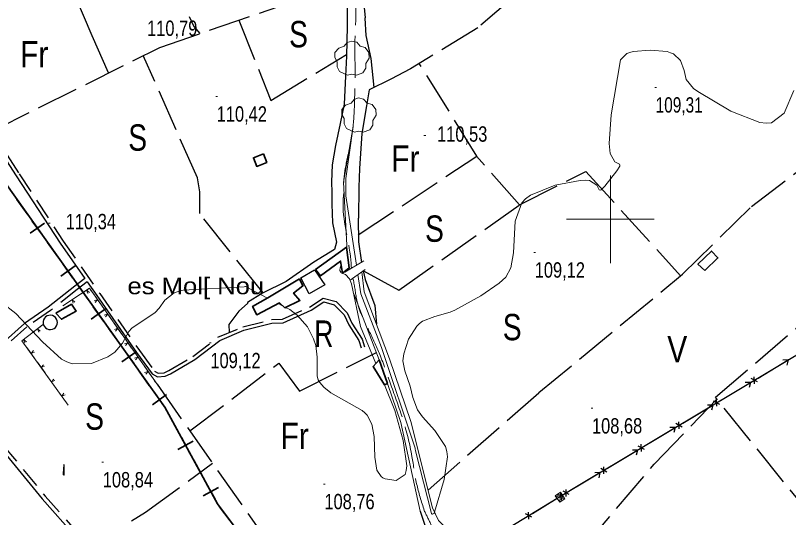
# Model space of a CAD drawing. Extents: x 483840 to 488445, y 4386047 to 4389027.
# Drawn here: x 486660.9 to 487101.5, y 4388330.1 to 4388616.1 of the extents above; entities that cross this region are included whole.
import ezdxf
from ezdxf.enums import TextEntityAlignment as Align

# ---------------------------------------------------------------- set-up
doc = ezdxf.new("R2010")
doc.units = 0
doc.header["$LTSCALE"] = 4
doc.linetypes.add('LONG_DASHED', pattern=[7.5, 6, -1.5])
doc.linetypes.add('MEDIUM_DASHED', pattern=[4.5, 3, -1.5])
for name, color, linetype, lineweight in [('1', 7, 'Continuous', 13), ('15', 7, 'LONG_DASHED', 13), ('21', 7, 'Continuous', 25), ('24', 7, 'Continuous', 13), ('25', 7, 'LONG_DASHED', 25), ('29', 7, 'Continuous', 13), ('34', 7, 'Continuous', 35), ('38', 7, 'Continuous', 25), ('41', 7, 'Continuous', 13), ('43', 7, 'Continuous', 25), ('47', 7, 'Continuous', 35), ('51', 7, 'Continuous', 13), ('7', 7, 'Continuous', 13), ('9', 7, 'Continuous', 13)]:
    doc.layers.add(name, color=color, linetype=linetype, lineweight=lineweight)
doc.layers.add('31', color=7, linetype='Continuous')
doc.layers.add('5', color=7, linetype='Continuous')

msp = doc.modelspace()

# ---------------------------------------------------------------- linework, layer by layer
at = {"layer": '1'}
for p, q in [((487000, 4388525), (487000, 4388475)), ((486975, 4388500), (487025, 4388500))]:
    msp.add_line(p, q, dxfattribs=at)
at = {"layer": '15'}
for points in [[(486849.66, 4388754.14), (486849.99, 4388746.91), (486849.28, 4388728.54), (486848.77, 4388709.12), (486848.57, 4388701.1), (486849.04, 4388682.03), (486851.97, 4388647.52), (486854.86, 4388620.35), (486854.3, 4388596.13), (486854.55, 4388582.85), (486854.32, 4388573.85), (486853.89, 4388560.28), (486853.23, 4388552.35), (486850.16, 4388535.39), (486848.09, 4388522.17), (486847.95, 4388514.07), (486847.85, 4388513.17), (486851.77, 4388479.23), (486852.31, 4388473.01), (486852.35, 4388472.07)], [(486853.15, 4388466.36), (486853.31, 4388465.8), (486855.39, 4388454.15), (486862.36, 4388436.56), (486868.53, 4388423.04), (486874.83, 4388405.77), (486881.74, 4388385.93), (486886.89, 4388364.94), (486889.56, 4388349.27), (486893.89, 4388334.15)], [(486893.89, 4388334.15), (486897.66, 4388326.32), (486901.59, 4388318.79), (486916.3, 4388301.6), (486931.17, 4388285), (486946.06, 4388266.23), (486961.18, 4388241.83), (486971.4, 4388222.35), (486976.88, 4388216.51), (486980.74, 4388214.98), (487014.75, 4388198.86), (487062.09, 4388181.42), (487106.44, 4388161.57), (487118.06, 4388158.42), (487129.84, 4388155.41), (487144.86, 4388153.07), (487183.1, 4388149.22), (487219.15, 4388147.67), (487249.69, 4388145.15), (487284.01, 4388143.35), (487309.63, 4388139.15), (487338.91, 4388136.81), (487373.52, 4388134.78), (487389.56, 4388131.36), (487412.81, 4388128.2), (487439.22, 4388122.11), (487454.85, 4388120.2), (487484.81, 4388118.29), (487497.1, 4388117.82), (487512.45, 4388113.59), (487528.23, 4388111.76), (487540.59, 4388110.91), (487570.91, 4388108.31), (487614.32, 4388104.25), (487633.02, 4388104.89), (487633.64, 4388105.77), (487646.19, 4388109.42), (487658.59, 4388110.15), (487671.71, 4388109.8), (487682.88, 4388109.36), (487684.71, 4388109.3)]]:
    msp.add_spline(points, degree=3, dxfattribs=at)
at = {"layer": '21'}
for points in [[(486823.45, 4388466.62), (486831.38, 4388471.21), (486837.23, 4388462.58), (486828.24, 4388457.64)], [(486684.75, 4388441.25), (486684.62, 4388442.26), (486684.25, 4388443.21), (486683.64, 4388444.04), (486682.86, 4388444.69), (486681.93, 4388445.12), (486680.93, 4388445.32), (486679.91, 4388445.25), (486678.94, 4388444.94), (486678.07, 4388444.39), (486677.37, 4388443.64), (486676.88, 4388442.75), (486676.63, 4388441.76), (486676.63, 4388440.74), (486676.88, 4388439.75), (486677.37, 4388438.85), (486678.07, 4388438.1), (486678.94, 4388437.56), (486679.91, 4388437.24), (486680.93, 4388437.18), (486681.93, 4388437.37), (486682.86, 4388437.8), (486683.64, 4388438.45), (486684.25, 4388439.28), (486684.62, 4388440.23)]]:
    msp.add_lwpolyline(points, close=True, dxfattribs=at)
at = {"layer": '24'}
for p, q in [((486689.98, 4388452.03), (486696.23, 4388456.19)), ((486705.53, 4388457.31), (486709.84, 4388451.17)), ((486711.28, 4388449.13), (486715.59, 4388443)), ((486670.42, 4388435.34), (486676.37, 4388439.9)), ((486717.02, 4388440.96), (486721.34, 4388434.83)), ((486722.77, 4388432.79), (486727.08, 4388426.66)), ((486671.93, 4388420.6), (486667.56, 4388426.7)), ((486728.52, 4388424.62), (486732.83, 4388418.48)), ((486677.76, 4388412.49), (486673.39, 4388418.58)), ((486734.26, 4388416.45), (486738.58, 4388410.31)), ((486683.58, 4388404.37), (486679.21, 4388410.46)), ((486740.01, 4388408.28), (486741.59, 4388406.03)), ((486689.41, 4388396.25), (486685.04, 4388402.35))]:
    msp.add_line(p, q, dxfattribs=at)
for points in [[(486687.91, 4388450.65), (486703.1, 4388460.76), (486741.59, 4388406.03)], [(486698.3, 4388457.56), (486703.1, 4388460.76), (486704.1, 4388459.34)], [(486702.98, 4388458.28), (486701.42, 4388459.64), (486702.09, 4388457.68)], [(486694.66, 4388452.74), (486693.1, 4388454.11), (486693.77, 4388452.15)], [(486706.36, 4388452.65), (486707.69, 4388454.24), (486705.75, 4388453.52)], [(486712.11, 4388444.47), (486713.43, 4388446.07), (486711.49, 4388445.35)], [(486690.86, 4388394.23), (486664.58, 4388430.85), (486676.68, 4388440.14)], [(486675.04, 4388436.36), (486673.4, 4388437.62), (486674.19, 4388435.71)], [(486717.85, 4388436.3), (486719.18, 4388437.9), (486717.24, 4388437.18)], [(486666.11, 4388428.72), (486664.58, 4388430.85), (486668.45, 4388433.82)], [(486667.12, 4388430.28), (486665.47, 4388431.54), (486666.27, 4388429.63)], [(486723.6, 4388428.13), (486724.93, 4388429.72), (486722.99, 4388429.01)], [(486671.06, 4388425.25), (486669.75, 4388423.65), (486671.68, 4388424.38)], [(486729.35, 4388419.96), (486730.67, 4388421.55), (486728.73, 4388420.83)], [(486676.88, 4388417.14), (486675.57, 4388415.53), (486677.51, 4388416.27)], [(486735.1, 4388411.79), (486736.42, 4388413.38), (486734.48, 4388412.66)], [(486682.71, 4388409.02), (486681.4, 4388407.42), (486683.33, 4388408.15)], [(486688.53, 4388400.9), (486687.22, 4388399.3), (486689.16, 4388400.04)]]:
    msp.add_lwpolyline(points, dxfattribs=at)
at = {"layer": '25'}
msp.add_line((486741.59, 4388406.03), (486828.11, 4388283.05), dxfattribs=at)
for points in [[(486856.08, 4388754.13), (486855.69, 4388740.98), (486855.21, 4388720.06), (486854.68, 4388702.44), (486854.45, 4388679.56), (486854.56, 4388666.21), (486854.88, 4388655.69), (486856.06, 4388643.51), (486858.7, 4388629.63), (486860.19, 4388614.66), (486860.11, 4388614.59), (486860.52, 4388604.68), (486863.48, 4388591.62), (486865.19, 4388575.07)], [(487095.92, 4388753.66), (487093.51, 4388751.57), (487022.8, 4388690.39), (486967.09, 4388645.86), (486924.34, 4388609.08), (486886.14, 4388585.77), (486874.8, 4388579.77), (486862.57, 4388573.78), (486860.98, 4388564.6), (486858.24, 4388548.84), (486856.97, 4388528.91), (486856.69, 4388518.27), (486856.39, 4388500.87), (486856.22, 4388500.27), (486856.33, 4388487.21), (486858.06, 4388475.47)], [(486729.8, 4388674.15), (486747.17, 4388642.6), (486762.52, 4388609.86), (486766.01, 4388605.77)], [(486713.92, 4388583.33), (486704.53, 4388604.4), (486694.85, 4388627.24), (486681.62, 4388654.36)], [(486647.24, 4388550.04), (486743.15, 4388597.92), (486810.38, 4388620.99), (486847.91, 4388638.41)], [(486849.86, 4388624.46), (486850.01, 4388609.98), (486849.49, 4388592.81), (486849.04, 4388581.57), (486848.17, 4388565.53), (486846.01, 4388554.49), (486843.35, 4388541.95), (486841.34, 4388530.97), (486841.01, 4388521.3), (486841.16, 4388515.3), (486841.15, 4388515.07), (486841.28, 4388508.54), (486841.68, 4388497.95), (486843.79, 4388486.94), (486842.71, 4388482.77), (486831.04, 4388475.65), (486815.22, 4388464.58), (486801.76, 4388457.88), (486793.07, 4388452.55), (486793.14, 4388452.1), (486788.22, 4388447.65), (486782.47, 4388440.15), (486782.7, 4388435.51)], [(487041.09, 4388468.73), (487080.44, 4388507.31), (487121.24, 4388538.36), (487150.3, 4388564.84), (487182.93, 4388593.17), (487216.3, 4388621.18), (487234.26, 4388625.25)], [(486788.11, 4388613.35), (486806.51, 4388567.67), (486849.53, 4388593.86)], [(486802.08, 4388458.05), (486765.89, 4388503.23), (486765.99, 4388515.69), (486764.54, 4388523.6), (486733.73, 4388593.22)], [(486856.3, 4388491.12), (486923.86, 4388536.02), (486891.03, 4388588.76)], [(486859.22, 4388470.72), (486879.32, 4388459.68), (486948.11, 4388508.22), (486923.74, 4388535.94)], [(486948.11, 4388508.22), (486986.05, 4388527.26), (487040.02, 4388467.85)], [(486988.11, 4388217.41), (487025.56, 4388253.5), (487095.35, 4388311.32), (487117.6, 4388327.17), (487059.89, 4388398.61), (487108.09, 4388439.89), (487155.86, 4388479.31)], [(486859.07, 4388470.61), (486860.12, 4388465.66), (486865.66, 4388450.81), (486866.6, 4388440.34)], [(486896.05, 4388345.8), (486959.27, 4388401.31), (487041.09, 4388468.73)], [(486760.29, 4388379.46), (486811, 4388418.02), (486822.74, 4388402.18), (486866.62, 4388424.18)], [(486947.98, 4388269.39), (486984.04, 4388312.43), (487024.98, 4388360.58), (487060.72, 4388397.59)], [(486701.62, 4388312.23), (486735.03, 4388333.2), (486773.25, 4388361.04)], [(486891.56, 4388333.76), (486893.99, 4388326.42), (486899.08, 4388314.5), (486914.46, 4388297.37), (486924.6, 4388286.23), (486930.33, 4388278.65), (486942.48, 4388264.07), (486954.76, 4388245.82), (486963.92, 4388228.78), (486969.57, 4388214.3)]]:
    msp.add_lwpolyline(points, dxfattribs=at)
at = {"layer": '29'}
for points in [[(486850.14, 4388582.11), (486845.6, 4388584.23), (486844.19, 4388586.77), (486844.29, 4388589.75), (486842.92, 4388592.16), (486842.96, 4388594.91), (486845.12, 4388597.51), (486848.31, 4388598.51), (486849.96, 4388600.7), (486852.53, 4388601.53), (486855.39, 4388600.88), (486857.34, 4388598.61), (486860.15, 4388597.79), (486862.28, 4388594.94), (486862.52, 4388591.81), (486860.64, 4388588.66), (486860.64, 4388585.98), (486858.82, 4388583.37), (486855.2, 4388582.03), (486852.43, 4388582.66)], [(486854.1, 4388549.67), (486849.56, 4388551.79), (486848.15, 4388554.33), (486848.25, 4388557.31), (486846.88, 4388559.72), (486846.92, 4388562.47), (486849.08, 4388565.07), (486852.27, 4388566.07), (486853.92, 4388568.26), (486856.49, 4388569.09), (486859.35, 4388568.44), (486861.3, 4388566.17), (486864.11, 4388565.35), (486866.24, 4388562.5), (486866.48, 4388559.37), (486864.6, 4388556.22), (486864.6, 4388553.54), (486862.78, 4388550.93), (486859.16, 4388549.59), (486856.39, 4388550.22)]]:
    msp.add_lwpolyline(points, close=True, dxfattribs=at)
at = {"layer": '34'}
for p, q in [((486661.73, 4388511.22), (486667.54, 4388503.08)), ((486670.43, 4388499.02), (486676.24, 4388490.88)), ((486677.41, 4388497.85), (486669.26, 4388492.04)), ((486679.14, 4388486.8), (486684.94, 4388478.66)), ((486694.81, 4388473.43), (486686.67, 4388467.62)), ((486687.84, 4388474.6), (486693.64, 4388466.45)), ((486696.55, 4388462.38), (486702.35, 4388454.24)), ((486705.25, 4388450.18), (486711.05, 4388442.03)), ((486712.22, 4388449.01), (486704.08, 4388443.2)), ((486713.95, 4388437.96), (486719.76, 4388429.82)), ((486729.63, 4388424.58), (486721.48, 4388418.78)), ((486722.65, 4388425.75), (486728.46, 4388417.61)), ((486731.36, 4388413.54), (486737.16, 4388405.4)), ((486747.03, 4388400.16), (486738.89, 4388394.36)), ((486740.06, 4388401.33), (486745.86, 4388393.19)), ((486748.28, 4388388.81), (486753.07, 4388380.04)), ((486755.46, 4388375.66), (486760.25, 4388366.88)), ((486762.24, 4388373.66), (486753.47, 4388368.87)), ((486762.64, 4388362.49), (486767.43, 4388353.71)), ((486769.82, 4388349.33), (486774.61, 4388340.55)), ((486776.61, 4388347.33), (486767.83, 4388342.54)), ((486777.26, 4388336.32), (486783.26, 4388328.32))]:
    msp.add_line(p, q, dxfattribs=at)
msp.add_lwpolyline([(486520.9, 4388755.72), (486603, 4388633), (486612, 4388581), (486746, 4388393), (486776, 4388338), (486812, 4388290), (486879, 4388250), (487017, 4388189), (487152, 4388148), (487234, 4388140), (487360, 4387899), (487497, 4387717), (487531, 4387660), (487608, 4387440), (487634, 4387181), (487675, 4387065), (487547, 4387001), (487350, 4386921), (487175, 4386900), (487110, 4386912), (487380, 4386493), (487280.6, 4386441.97)], dxfattribs=at)
at = {"layer": '38'}
for points in [[(486608.86, 4388600.41), (486622.27, 4388583.14), (486644.52, 4388550.45), (486661.33, 4388524.8), (486686.29, 4388486.48), (486700.41, 4388466.24)], [(486700.41, 4388466.24), (486694.65, 4388461.88), (486679.56, 4388449.89), (486665.96, 4388440.57), (486653.28, 4388429.27), (486645.87, 4388421.06), (486640.63, 4388412.95), (486639.39, 4388405.78), (486638.99, 4388393.33), (486639.78, 4388386.18), (486651.96, 4388370.03), (486676.11, 4388340.82), (486695.35, 4388319.08), (486699.64, 4388311.16)], [(486701.69, 4388464.39), (486707.19, 4388456.52), (486729.83, 4388424.05), (486738.81, 4388411.96), (486741.77, 4388410.3), (486746.13, 4388410.56), (486749.25, 4388412.06), (486763.11, 4388420.1), (486777.35, 4388431.06), (486791.08, 4388436.77), (486807.1, 4388440.86), (486813.56, 4388441.06), (486829.5, 4388448.15), (486836.6, 4388452.92), (486842.56, 4388451.33), (486848.19, 4388445.56), (486850.89, 4388439.86), (486856.66, 4388430.93), (486857.9, 4388426.7)]]:
    msp.add_lwpolyline(points, dxfattribs=at)
at = {"layer": '38', "linetype": 'MEDIUM_DASHED'}
for points in [[(486610.19, 4388602), (486623.93, 4388584.35), (486646.22, 4388551.59), (486663.05, 4388525.92), (486687.99, 4388487.63), (486708.87, 4388457.69), (486731.49, 4388425.25), (486740.19, 4388413.53), (486742.25, 4388412.38), (486745.61, 4388412.58), (486748.29, 4388413.87), (486761.97, 4388421.81), (486776.31, 4388432.85), (486790.43, 4388438.72), (486806.81, 4388442.9), (486813.09, 4388443.1), (486828.5, 4388449.95), (486836.23, 4388455.14), (486843.63, 4388453.17), (486849.9, 4388446.75), (486852.68, 4388440.86), (486858.54, 4388431.79), (486859.87, 4388427.28)], [(486701.69, 4388464.39), (486696.03, 4388460.1), (486680.9, 4388448.08), (486667.35, 4388438.8), (486654.87, 4388427.67), (486647.66, 4388419.69), (486642.77, 4388412.12), (486641.63, 4388405.55), (486641.24, 4388393.42), (486641.95, 4388387.04), (486653.72, 4388371.42), (486677.82, 4388342.28), (486697.2, 4388320.38), (486701.62, 4388312.23)]]:
    msp.add_lwpolyline(points, dxfattribs=at)
at = {"layer": '41'}
for p, q in [((486848.67, 4388469.86), (486859.49, 4388476.33)), ((486851.57, 4388465.29), (486860.12, 4388471.36))]:
    msp.add_line(p, q, dxfattribs=at)
at = {"layer": '43'}
for p, q in [((487084.18, 4388409.61), (487101.34, 4388419.87)), ((487101.34, 4388419.87), (487098.34, 4388419.83)), ((487101.34, 4388419.87), (487100.61, 4388416.97)), ((487062.72, 4388396.79), (487079.88, 4388407.05)), ((487079.88, 4388407.05), (487076.88, 4388407)), ((487079.88, 4388407.05), (487079.15, 4388404.14)), ((487083.78, 4388407.35), (487080.29, 4388409.29)), ((487082.06, 4388406.32), (487082.01, 4388410.32)), ((487060.61, 4388393.5), (487060.55, 4388397.49)), ((487041.26, 4388383.96), (487058.43, 4388394.22)), ((487058.43, 4388394.22), (487055.42, 4388394.17)), ((487058.43, 4388394.22), (487057.69, 4388391.31)), ((487062.32, 4388394.52), (487058.83, 4388396.47)), ((487039.15, 4388380.67), (487039.09, 4388384.66)), ((487019.8, 4388371.13), (487036.97, 4388381.39)), ((487036.97, 4388381.39), (487033.97, 4388381.35)), ((487036.97, 4388381.39), (487036.24, 4388378.49)), ((487040.86, 4388381.7), (487037.37, 4388383.64)), ((487019.41, 4388368.87), (487015.91, 4388370.81)), ((487017.69, 4388367.84), (487017.63, 4388371.84)), ((486998.34, 4388358.3), (487015.51, 4388368.57)), ((487015.51, 4388368.57), (487012.51, 4388368.52)), ((487015.51, 4388368.57), (487014.78, 4388365.66)), ((486997.95, 4388356.04), (486994.46, 4388357.98)), ((486996.23, 4388355.01), (486996.17, 4388359.01)), ((486976.88, 4388345.48), (486994.05, 4388355.74)), ((486994.05, 4388355.74), (486991.05, 4388355.69)), ((486994.05, 4388355.74), (486993.32, 4388352.83)), ((486976.49, 4388343.21), (486973, 4388345.16)), ((486974.77, 4388342.19), (486974.71, 4388346.18)), ((486972.59, 4388342.91), (486969.59, 4388342.86)), ((486972.59, 4388342.91), (486971.86, 4388340)), ((486955.12, 4388330.26), (486951.61, 4388332.18)), ((486953.41, 4388329.22), (486953.32, 4388333.22))]:
    msp.add_line(p, q, dxfattribs=at)
at = {"layer": '43', "lineweight": 13}
for p, q in [((486971.57, 4388344.55), (486971.12, 4388338.8)), ((486968.6, 4388342.56), (486974.09, 4388340.79))]:
    msp.add_line(p, q, dxfattribs=at)
at = {"layer": '43'}
for points in [[(486677.93, 4388163.47), (486969.73, 4388341.2), (487260.91, 4388515.26)], [(486955.5, 4388332.53), (486969.73, 4388341.2), (486972.59, 4388342.91)]]:
    msp.add_lwpolyline(points, dxfattribs=at)
at = {"layer": '43', "lineweight": 13}
msp.add_lwpolyline([(486968.6, 4388342.56), (486971.57, 4388344.55), (486974.09, 4388340.79), (486971.12, 4388338.8)], close=True, dxfattribs=at)
at = {"layer": '47'}
for points in [[(486802.19, 4388537.25), (486804.1, 4388532.38), (486798.4, 4388530.14), (486796.49, 4388535.01)], [(486831.83, 4388471.42), (486834.66, 4388467.75), (486846.21, 4388476.22), (486847.31, 4388469.29), (486851.14, 4388472.34), (486849.49, 4388484.09)], [(487053.75, 4388470.87), (487061.29, 4388478.03), (487057.63, 4388481.86), (487049.93, 4388474.52)], [(486822.77, 4388466.18), (486804.77, 4388455.32), (486796.02, 4388450.38), (486798.44, 4388445.59), (486811.37, 4388452.38), (486814.38, 4388449.6), (486823.04, 4388453.8), (486819.4, 4388457.94), (486824.76, 4388462.08)], [(486683.9, 4388446.55), (486692.73, 4388451.58), (486695.48, 4388447.68), (486687.03, 4388443.1)], [(486868.23, 4388419.98), (486864.68, 4388416.24), (486871.23, 4388405.72), (486872.9, 4388406.57)]]:
    msp.add_lwpolyline(points, close=True, dxfattribs=at)
at = {"layer": '51'}
msp.add_line((486868.23, 4388419.98), (486853.75, 4388457.49), dxfattribs=at)
for points in [[(486858.4, 4388470.14), (486859.63, 4388458.69), (486874.09, 4388420.57), (486886.21, 4388384.77), (486898.59, 4388335.75), (486902, 4388328.46), (486905.8, 4388324.61), (486940.35, 4388280.34), (486951.2, 4388264.75), (486978.73, 4388221.34), (487043.81, 4388194.05), (487111.6, 4388166.69)], [(486891.56, 4388333.76), (486880.57, 4388384.24), (486872.86, 4388406.55)]]:
    msp.add_lwpolyline(points, dxfattribs=at)
at = {"layer": '7'}
for p, q in [((487025.29, 4388575.14), (487026.29, 4388575.14)), ((486775.08, 4388569.98), (486776.08, 4388569.98)), ((486893.72, 4388547.67), (486894.72, 4388547.67)), ((486679.71, 4388497.82), (486680.71, 4388497.82)), ((486956.36, 4388481.13), (486957.36, 4388481.13)), ((486771.49, 4388429.55), (486772.49, 4388429.55)), ((486989, 4388392.35), (486990, 4388392.35)), ((486710.14, 4388361.67), (486711.14, 4388361.67)), ((486836.46, 4388349.22), (486837.46, 4388349.22))]:
    msp.add_line(p, q, dxfattribs=at)
at = {"layer": '9'}
for p, q in [((486813.14, 4388450.74), (486810.66, 4388452.01)), ((486813.15, 4388450.73), (486813.14, 4388450.74)), ((486813.16, 4388450.72), (486813.15, 4388450.73)), ((486813.18, 4388450.71), (486813.16, 4388450.72))]:
    msp.add_line(p, q, dxfattribs=at)
for points in [[(487104.65, 4388573.33), (487099.14, 4388560.45), (487091.83, 4388554.92), (487088.76, 4388554.75), (487085.24, 4388555.18), (487068.73, 4388561.64), (487049.93, 4388572.73), (487047.45, 4388574.57), (487043.26, 4388579.59), (487042.13, 4388584.67), (487039.98, 4388590.37), (487036.05, 4388594.16), (487034.3, 4388594.89), (487032.27, 4388595.47), (487022.59, 4388596.41), (487012.97, 4388595.56), (487010.99, 4388595.02), (487009.31, 4388594.35), (487005.69, 4388590.81), (487000.49, 4388559.53), (486999.35, 4388543.19), (486999.79, 4388537.38), (487002.51, 4388532.76), (487005.12, 4388531.44), (487005.36, 4388530.92), (487005.39, 4388530.32), (487003.76, 4388527.58), (486996.84, 4388518.82), (486994.67, 4388516.7), (486994.16, 4388516.66), (486993.69, 4388516.86), (486992.34, 4388519.53), (486988.02, 4388522.1), (486985.69, 4388522.22), (486982.86, 4388522.09), (486968.53, 4388519.52), (486954.36, 4388513.78), (486951.63, 4388511.66), (486949.42, 4388509.31), (486945.73, 4388498.9), (486944.7, 4388480.86), (486943.33, 4388472.29), (486940.34, 4388467.11), (486936.62, 4388463.65), (486926.15, 4388456.33), (486911.35, 4388448.31), (486908.58, 4388447.15), (486899.85, 4388444.67), (486892.87, 4388441.99), (486891.2, 4388440.7), (486889.64, 4388439.17), (486884.95, 4388431.65), (486882.22, 4388423.38), (486881.75, 4388419.48), (486882.8, 4388413.67), (486885.87, 4388405.01), (486887.37, 4388398.52), (486890.11, 4388391.47), (486892.83, 4388387.4), (486899.96, 4388379.74), (486905.97, 4388370.68), (486906.73, 4388367.75), (486907.11, 4388364.64)], [(486855.28, 4388473.81), (486849.19, 4388513.41), (486849.23, 4388523.14), (486853.31, 4388552.94), (486847.94, 4388521.17), (486849.89, 4388481.75), (486849.85, 4388481.54)], [(486846.59, 4388473.84), (486846.16, 4388472.9), (486845.96, 4388472.31), (486845.69, 4388470.8), (486846.25, 4388469.83), (486846.56, 4388469.58), (486846.95, 4388469.35), (486848.95, 4388468.58), (486851.24, 4388466.09), (486852.37, 4388463.17), (486857.62, 4388438.91), (486866.25, 4388417.89)], [(486907.11, 4388364.64), (486905.26, 4388351.87), (486899.67, 4388333.27), (486899.58, 4388332.75), (486899.52, 4388332.63), (486899.45, 4388332.53), (486899.05, 4388332.24), (486898.62, 4388332.09), (486898.45, 4388332.06), (486898.27, 4388332.09), (486898.17, 4388332.2), (486898.12, 4388332.27), (486898.03, 4388332.42), (486888.95, 4388368.1), (486888.8, 4388369.18), (486888.71, 4388369.47), (486888.65, 4388369.62), (486888.62, 4388369.71), (486869.52, 4388427.06), (486857.79, 4388457.52), (486856.1, 4388468.51)], [(486804.48, 4388455.16), (486793.23, 4388460.89), (486792.7, 4388461.49), (486792.27, 4388461.72), (486792.12, 4388461.74), (486791.96, 4388461.74), (486791.27, 4388461.58), (486756.42, 4388459.57), (486753.63, 4388458.9), (486751.25, 4388458.09), (486745.95, 4388453.99), (486742.74, 4388449.3), (486740.51, 4388447), (486727.16, 4388437.93), (486725.56, 4388436.03), (486721.89, 4388429.45), (486717.45, 4388424.23), (486713.61, 4388421.72), (486704.15, 4388417.87), (486693.12, 4388417.69), (486690.09, 4388418.79), (486687.06, 4388420.39), (486676.19, 4388430.28), (486661.12, 4388446.43), (486653.28, 4388452.34)], [(486871.24, 4388405.73), (486877.21, 4388391.17), (486881.91, 4388373.99), (486883.87, 4388359.59), (486883.6, 4388356.85), (486882.98, 4388354.65), (486877.82, 4388351.23), (486871.62, 4388352.2), (486870.33, 4388352.77), (486869.24, 4388353.47), (486866.89, 4388357.1), (486865.74, 4388364.43), (486865.33, 4388376.34), (486864.06, 4388383.29), (486861.27, 4388388.5), (486859.99, 4388389.84), (486858.5, 4388391.13), (486840.66, 4388401.12), (486836.69, 4388404.3), (486834.36, 4388407.1), (486833.51, 4388408.48), (486832.79, 4388410.66), (486832.76, 4388421.57), (486832.02, 4388428.2), (486830.83, 4388431.92), (486827.29, 4388438.75), (486821.54, 4388445.31), (486817.24, 4388448.65), (486814.88, 4388449.84)]]:
    msp.add_lwpolyline(points, dxfattribs=at)
msp.add_lwpolyline([(486688.66, 4388354.81), (486688.6, 4388360.2), (486688.56, 4388360.28), (486688.51, 4388360.18), (486688.03, 4388355.13), (486688.15, 4388354.42), (486688.36, 4388354.33), (486688.4, 4388354.33), (486688.44, 4388354.35), (486688.55, 4388354.5)], close=True, dxfattribs=at)

# ---------------------------------------------------------------- texts
at = {"layer": '31'}
for s, width, p in [('S', 0.8, (486822.22, 4388597.94)), ('Fr', 0.85, (486671.56, 4388586.51)), ('S', 0.8, (486730.53, 4388539.07)), ('Fr', 0.85, (486883.11, 4388527.05)), ('S', 0.8, (486899.72, 4388487.18)), ('S', 0.8, (486944.02, 4388431.11)), ('R', 0.75, (486836.62, 4388427.36)), ('V', 0.85, (487038.11, 4388418.5)), ('S', 0.8, (486705.96, 4388380.16)), ('Fr', 0.85, (486820.01, 4388369.08))]:
    msp.add_text(s, height=15, dxfattribs=dict(at, width=width)).set_placement(p, align=Align.CENTER)
at = {"layer": '5', "width": 1.15}
msp.add_text('es Mol[ Nou', height=9.5, dxfattribs=at).set_placement((486802.65, 4388457.3), align=Align.RIGHT)
at = {"layer": '7'}
for s, width, p in [('110,79', 0.8, (486735.9, 4388604.44)), ('109,31', 0.75, (487025.79, 4388560.77)), ('110,42', 0.8, (486775.58, 4388555.61)), ('110,53', 0.8, (486901.22, 4388544.19)), ('110,34', 0.8, (486689.53, 4388494.33)), ('109,12', 0.8, (486956.86, 4388466.76)), ('109,12', 0.8, (486771.99, 4388415.18)), ('108,68', 0.8, (486989.5, 4388377.98)), ('108,84', 0.8, (486710.64, 4388347.3)), ('108,76', 0.8, (486836.96, 4388334.85))]:
    msp.add_text(s, height=8.75, dxfattribs=dict(at, width=width)).set_placement(p)

doc.saveas('drawing.dxf')
